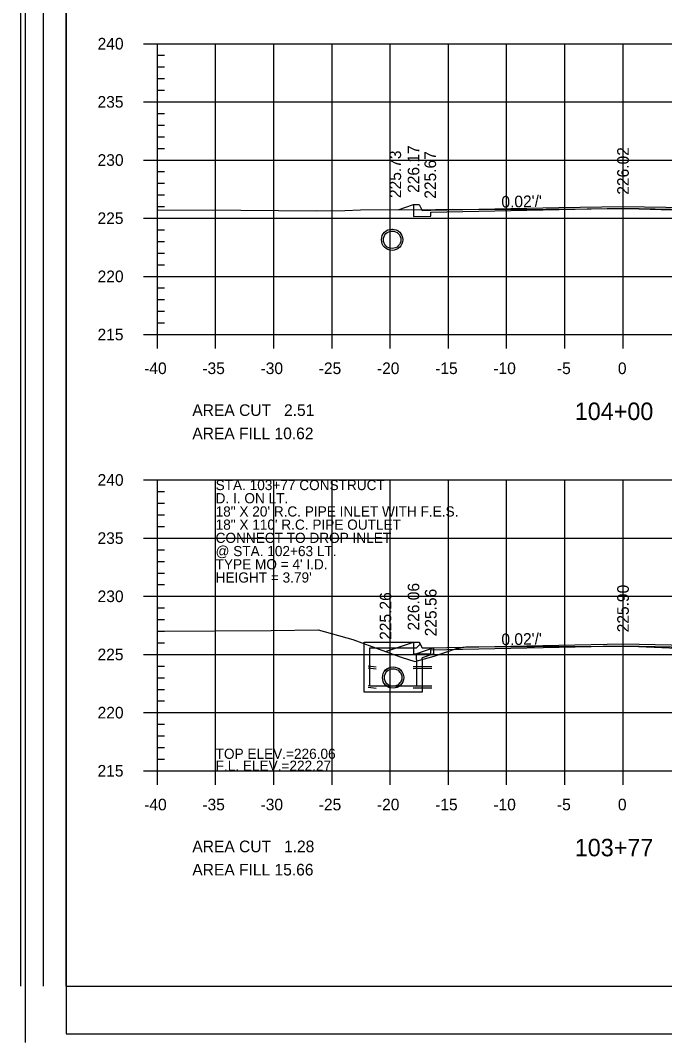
# Model space of a CAD drawing. Extents: x 1367903 to 1373764, y 376865 to 382130.
# Drawn here: x 1370689.3 to 1370800, y 377279.1 to 377454.8 of the extents above; entities that cross this region are included whole.
import ezdxf

# ---------------------------------------------------------------- set-up
doc = ezdxf.new("R2010")
doc.units = 0
for name, color, linetype in [('R_Axis', 7, 'Continuous'), ('R_Axis Annot', 7, 'Continuous'), ('R_Border', 7, 'Continuous'), ('R_Border PE', 7, 'Continuous'), ('R_Draft', 7, 'Continuous'), ('R_Exist Surface', 7, 'Continuous'), ('R_Fin Surface', 7, 'Continuous'), ('R_Fin Surface Annot', 7, 'Continuous'), ('R_Grid', 7, 'Continuous'), ('R_Water', 7, 'Continuous'), ('R_Water Annot', 7, 'Continuous')]:
    doc.layers.add(name, color=color, linetype=linetype)

msp = doc.modelspace()

# ---------------------------------------------------------------- linework, layer by layer
for p, q in [((1370748.37, 377347.95), (1370757.87, 377347.95)), ((1370748.37, 377344.95), (1370748.37, 377347.95)), ((1370758.03, 377347.62), (1370757.37, 377346.95)), ((1370758.03, 377347.62), (1370757.87, 377347.95)), ((1370749.37, 377344.95), (1370749.37, 377346.95)), ((1370749.37, 377346.95), (1370757.37, 377346.95)), ((1370760.37, 377346.99), (1370757.37, 377345.95)), ((1370757.37, 377344.95), (1370757.37, 377345.95)), ((1370760.37, 377345.93), (1370758.37, 377345.24)), ((1370758.37, 377344.95), (1370758.37, 377345.24))]:
    msp.add_line(p, q)
for points in [[(1370756.87, 377423.18), (1370756.87, 377422.52), (1370756.87, 377422.52), (1370756.87, 377421.15), (1370759.87, 377421.21), (1370759.87, 377421.88), (1370792.87, 377422.54), (1370825.87, 377421.88), (1370825.87, 377421.21), (1370828.87, 377421.15), (1370828.87, 377422.6), (1370842.87, 377422.88), (1370842.87, 377423.46)], [(1370756.87, 377347.95), (1370756.87, 377347.28), (1370756.87, 377347.28), (1370756.87, 377345.92), (1370759.87, 377345.98), (1370759.87, 377346.65), (1370792.87, 377347.31), (1370825.87, 377346.65), (1370825.87, 377345.98), (1370828.87, 377345.92), (1370828.87, 377347.36), (1370842.87, 377347.64), (1370842.87, 377348.23)], [(1370760.37, 377345.93), (1370760.37, 377346.99)]]:
    msp.add_lwpolyline(points)
at = {"layer": 'R_Axis'}
for p, q in [((1370710.47, 377450.84), (1370715.27, 377450.84)), ((1370712.87, 377400.84), (1370712.87, 377450.84)), ((1370712.87, 377448.84), (1370714.07, 377448.84)), ((1370712.87, 377446.84), (1370714.07, 377446.84)), ((1370712.87, 377444.84), (1370714.07, 377444.84)), ((1370712.87, 377442.84), (1370714.07, 377442.84)), ((1370710.47, 377440.84), (1370715.27, 377440.84)), ((1370712.87, 377438.84), (1370714.07, 377438.84)), ((1370712.87, 377436.84), (1370714.07, 377436.84)), ((1370712.87, 377434.84), (1370714.07, 377434.84)), ((1370712.87, 377432.84), (1370714.07, 377432.84)), ((1370710.47, 377430.84), (1370715.27, 377430.84)), ((1370712.87, 377428.84), (1370714.07, 377428.84)), ((1370712.87, 377426.84), (1370714.07, 377426.84)), ((1370712.87, 377424.84), (1370714.07, 377424.84)), ((1370712.87, 377422.84), (1370714.07, 377422.84)), ((1370710.47, 377420.84), (1370715.27, 377420.84)), ((1370712.87, 377418.84), (1370714.07, 377418.84)), ((1370712.87, 377416.84), (1370714.07, 377416.84)), ((1370712.87, 377414.84), (1370714.07, 377414.84)), ((1370712.87, 377412.84), (1370714.07, 377412.84)), ((1370710.47, 377410.84), (1370715.27, 377410.84)), ((1370712.87, 377408.84), (1370714.07, 377408.84)), ((1370712.87, 377406.84), (1370714.07, 377406.84)), ((1370712.87, 377404.84), (1370714.07, 377404.84)), ((1370712.87, 377398.44), (1370712.87, 377403.24)), ((1370712.87, 377402.84), (1370714.07, 377402.84)), ((1370722.87, 377398.44), (1370722.87, 377403.24)), ((1370732.87, 377398.44), (1370732.87, 377403.24)), ((1370742.87, 377398.44), (1370742.87, 377403.24)), ((1370752.87, 377398.44), (1370752.87, 377403.24)), ((1370762.87, 377398.44), (1370762.87, 377403.24)), ((1370772.87, 377398.44), (1370772.87, 377403.24)), ((1370782.87, 377398.44), (1370782.87, 377403.24)), ((1370792.87, 377398.44), (1370792.87, 377403.24)), ((1370710.47, 377400.84), (1370715.27, 377400.84)), ((1370712.87, 377400.84), (1370872.87, 377400.84)), ((1370710.47, 377375.84), (1370715.27, 377375.84)), ((1370712.87, 377325.84), (1370712.87, 377375.84)), ((1370712.87, 377373.84), (1370714.07, 377373.84)), ((1370712.87, 377371.84), (1370714.07, 377371.84)), ((1370712.87, 377369.84), (1370714.07, 377369.84)), ((1370712.87, 377367.84), (1370714.07, 377367.84)), ((1370710.47, 377365.84), (1370715.27, 377365.84)), ((1370712.87, 377363.84), (1370714.07, 377363.84)), ((1370712.87, 377361.84), (1370714.07, 377361.84)), ((1370712.87, 377359.84), (1370714.07, 377359.84)), ((1370712.87, 377357.84), (1370714.07, 377357.84)), ((1370710.47, 377355.84), (1370715.27, 377355.84)), ((1370712.87, 377353.84), (1370714.07, 377353.84)), ((1370712.87, 377351.84), (1370714.07, 377351.84)), ((1370712.87, 377349.84), (1370714.07, 377349.84)), ((1370712.87, 377347.84), (1370714.07, 377347.84)), ((1370710.47, 377345.84), (1370715.27, 377345.84)), ((1370712.87, 377343.84), (1370714.07, 377343.84)), ((1370712.87, 377341.84), (1370714.07, 377341.84)), ((1370712.87, 377339.84), (1370714.07, 377339.84)), ((1370712.87, 377337.84), (1370714.07, 377337.84)), ((1370710.47, 377335.84), (1370715.27, 377335.84)), ((1370712.87, 377333.84), (1370714.07, 377333.84)), ((1370712.87, 377331.84), (1370714.07, 377331.84)), ((1370712.87, 377329.84), (1370714.07, 377329.84)), ((1370712.87, 377323.44), (1370712.87, 377328.24)), ((1370712.87, 377327.84), (1370714.07, 377327.84)), ((1370722.87, 377323.44), (1370722.87, 377328.24)), ((1370732.87, 377323.44), (1370732.87, 377328.24)), ((1370742.87, 377323.44), (1370742.87, 377328.24)), ((1370752.87, 377323.44), (1370752.87, 377328.24)), ((1370762.87, 377323.44), (1370762.87, 377328.24)), ((1370772.87, 377323.44), (1370772.87, 377328.24)), ((1370782.87, 377323.44), (1370782.87, 377328.24)), ((1370792.87, 377323.44), (1370792.87, 377328.24)), ((1370710.47, 377325.84), (1370715.27, 377325.84)), ((1370712.87, 377325.84), (1370872.87, 377325.84))]:
    msp.add_line(p, q, dxfattribs=at)
at = {"layer": 'R_Border'}
for p, q in [((1370690.14, 377620.35), (1370690.14, 377279.12)), ((1370697.17, 377611.47), (1370697.17, 377280.59)), ((1370697.17, 377280.59), (1370901.49, 377280.59))]:
    msp.add_line(p, q, dxfattribs=at)
at = {"layer": 'R_Border PE'}
for p, q in [((1370689.33, 377610.76), (1370689.33, 377288.8)), ((1370693.25, 377610.76), (1370693.25, 377288.8)), ((1370697.17, 377288.8), (1370697.17, 377603.25)), ((1370697.17, 377288.8), (1370901.49, 377288.8))]:
    msp.add_line(p, q, dxfattribs=at)
at = {"layer": 'R_Exist Surface'}
for points in [[(1370712.87, 377422.27), (1370712.99, 377422.27), (1370727.18, 377422.21), (1370740.13, 377422.11), (1370745.07, 377422.14), (1370747.76, 377422.25), (1370760.67, 377422.34), (1370762.22, 377422.34), (1370762.23, 377422.34), (1370763.5, 377422.38), (1370772.68, 377422.35), (1370793.72, 377422.5), (1370801.33, 377422.29)], [(1370712.87, 377349.87), (1370732.39, 377349.96), (1370740.51, 377350.07), (1370746.45, 377348.41), (1370751.41, 377346.59), (1370754.74, 377345.36), (1370757.1, 377344.61), (1370760.4, 377345.52), (1370764.25, 377346.84), (1370764.41, 377346.88), (1370765.86, 377347.14), (1370789.45, 377347.26), (1370794.18, 377347.28), (1370799.52, 377347.03), (1370824.15, 377345.97), (1370826.34, 377345.73), (1370839.08, 377345.71), (1370843.6, 377345.67), (1370845.88, 377345.51), (1370849.36, 377345.47), (1370861.41, 377344.89), (1370867.07, 377344.65), (1370871.28, 377344.49), (1370872.87, 377344.43)]]:
    msp.add_lwpolyline(points, dxfattribs=at)
at = {"layer": 'R_Fin Surface'}
for points in [[(1370754.21, 377422.3), (1370756.87, 377423.18), (1370757.87, 377423.18), (1370758.37, 377422.18), (1370759.87, 377422.21), (1370781.87, 377422.65), (1370792.87, 377422.87), (1370803.87, 377422.65), (1370825.87, 377422.21), (1370827.37, 377422.18), (1370827.87, 377423.18), (1370828.87, 377423.18), (1370832.87, 377423.26), (1370842.87, 377423.46), (1370850.83, 377420.81)], [(1370752.06, 377346.35), (1370756.87, 377347.95), (1370757.87, 377347.95), (1370758.37, 377346.95), (1370759.87, 377346.98), (1370781.87, 377347.42), (1370792.87, 377347.64), (1370803.87, 377347.42), (1370825.87, 377346.98), (1370827.37, 377346.95), (1370827.87, 377347.95), (1370828.87, 377347.95), (1370832.87, 377348.03), (1370842.87, 377348.23), (1370851.44, 377345.37)]]:
    msp.add_lwpolyline(points, dxfattribs=at)
at = {"layer": 'R_Grid'}
for p, q in [((1370712.87, 377450.84), (1370872.87, 377450.84)), ((1370712.87, 377400.84), (1370712.87, 377450.84)), ((1370722.87, 377400.84), (1370722.87, 377450.84)), ((1370732.87, 377400.84), (1370732.87, 377450.84)), ((1370742.87, 377400.84), (1370742.87, 377450.84)), ((1370752.87, 377400.84), (1370752.87, 377450.84)), ((1370762.87, 377400.84), (1370762.87, 377450.84)), ((1370772.87, 377400.84), (1370772.87, 377450.84)), ((1370782.87, 377400.84), (1370782.87, 377450.84)), ((1370792.87, 377400.84), (1370792.87, 377450.84)), ((1370712.87, 377440.84), (1370872.87, 377440.84)), ((1370712.87, 377430.84), (1370872.87, 377430.84)), ((1370712.87, 377420.84), (1370872.87, 377420.84)), ((1370712.87, 377410.84), (1370872.87, 377410.84)), ((1370712.87, 377400.84), (1370872.87, 377400.84)), ((1370712.87, 377375.84), (1370872.87, 377375.84)), ((1370712.87, 377325.84), (1370712.87, 377375.84)), ((1370722.87, 377325.84), (1370722.87, 377375.84)), ((1370732.87, 377325.84), (1370732.87, 377375.84)), ((1370742.87, 377325.84), (1370742.87, 377375.84)), ((1370752.87, 377325.84), (1370752.87, 377375.84)), ((1370762.87, 377325.84), (1370762.87, 377375.84)), ((1370772.87, 377325.84), (1370772.87, 377375.84)), ((1370782.87, 377325.84), (1370782.87, 377375.84)), ((1370792.87, 377325.84), (1370792.87, 377375.84)), ((1370712.87, 377365.84), (1370872.87, 377365.84)), ((1370712.87, 377355.84), (1370872.87, 377355.84)), ((1370712.87, 377345.84), (1370872.87, 377345.84)), ((1370712.87, 377335.84), (1370872.87, 377335.84)), ((1370712.87, 377325.84), (1370872.87, 377325.84))]:
    msp.add_line(p, q, dxfattribs=at)
at = {"layer": 'R_Water'}
for p, q in [((1370753.2, 377418.99), (1370753.21, 377418.94)), ((1370753.2, 377418.66), (1370753.21, 377418.61)), ((1370753.2, 377415.66), (1370753.21, 377415.61)), ((1370753.2, 377415.32), (1370753.21, 377415.27)), ((1370749.07, 377343.87), (1370750.43, 377343.71)), ((1370760.04, 377343.73), (1370756.8, 377343.71)), ((1370749.07, 377343.53), (1370750.43, 377343.38)), ((1370760.04, 377343.4), (1370756.8, 377343.38)), ((1370749.07, 377340.53), (1370750.43, 377340.38)), ((1370749.07, 377340.2), (1370750.43, 377340.04)), ((1370760.04, 377340.4), (1370756.8, 377340.38)), ((1370760.04, 377340.06), (1370756.8, 377340.04))]:
    msp.add_line(p, q, dxfattribs=at)
for points in [[(1370758.37, 377344.95), (1370758.37, 377339.37), (1370753.37, 377339.37), (1370748.37, 377339.37), (1370748.37, 377344.95)], [(1370757.37, 377344.95), (1370757.37, 377340.37), (1370753.37, 377340.37), (1370749.37, 377340.37), (1370749.37, 377344.95)]]:
    msp.add_lwpolyline(points, dxfattribs=at)
for centre, radius in [((1370753.2, 377417.13), 1.83), ((1370753.2, 377417.13), 1.5), ((1370753.37, 377341.88), 1.83), ((1370753.37, 377341.87), 1.83), ((1370753.37, 377341.88), 1.5), ((1370753.37, 377341.87), 1.5)]:
    msp.add_circle(centre, radius, dxfattribs=at)

# ---------------------------------------------------------------- texts
at = {"layer": 'R_Axis Annot'}
for s, height, p in [('240', 2, (1370702.59, 377449.84)), ('235', 2, (1370702.58, 377439.84)), ('230', 2, (1370702.59, 377429.84)), ('225', 2, (1370702.58, 377419.84)), ('220', 2, (1370702.59, 377409.84)), ('215', 2, (1370702.58, 377399.84)), ('-40', 2, (1370710.59, 377394.04)), ('-35', 2, (1370720.59, 377394.04)), ('-30', 2, (1370730.59, 377394.04)), ('-25', 2, (1370740.59, 377394.04)), ('-20', 2, (1370750.59, 377394.04)), ('-15', 2, (1370760.59, 377394.04)), ('-10', 2, (1370770.59, 377394.04)), ('-5', 2, (1370781.52, 377394.04)), ('0', 2, (1370791.99, 377394.04)), ('AREA CUT   2.51', 2, (1370718.87, 377386.84)), ('104+00', 3, (1370784.58, 377386.14)), ('AREA FILL 10.62', 2, (1370718.87, 377382.84)), ('240', 2, (1370702.59, 377374.84)), ('235', 2, (1370702.58, 377364.84)), ('230', 2, (1370702.59, 377354.84)), ('225', 2, (1370702.58, 377344.84)), ('220', 2, (1370702.59, 377334.84)), ('215', 2, (1370702.58, 377324.84)), ('-40', 2, (1370710.59, 377319.04)), ('-35', 2, (1370720.59, 377319.04)), ('-30', 2, (1370730.59, 377319.04)), ('-25', 2, (1370740.59, 377319.04)), ('-20', 2, (1370750.59, 377319.04)), ('-15', 2, (1370760.59, 377319.04)), ('-10', 2, (1370770.59, 377319.04)), ('-5', 2, (1370781.52, 377319.04)), ('0', 2, (1370791.99, 377319.04)), ('AREA CUT   1.28', 2, (1370718.87, 377311.84)), ('103+77', 3, (1370784.58, 377311.14)), ('AREA FILL 15.66', 2, (1370718.87, 377307.84))]:
    msp.add_text(s, height=height, dxfattribs=at).set_placement(p)
at = {"layer": 'R_Draft'}
for s, p in [('STA. 103+77 CONSTRUCT', (1370722.87, 377374.09)), ('D. I. ON LT.', (1370722.87, 377371.82)), ('18" X 20\' R.C. PIPE INLET WITH F.E.S.', (1370722.87, 377369.55)), ('18" X 110\' R.C. PIPE OUTLET', (1370722.87, 377367.28)), ('CONNECT TO DROP INLET', (1370722.87, 377365.01)), ('@ STA. 102+63 LT.', (1370722.87, 377362.74)), ("TYPE MO = 4' I.D.", (1370722.87, 377360.47)), ("HEIGHT = 3.79'", (1370722.87, 377358.2))]:
    msp.add_text(s, height=1.75, dxfattribs=at).set_placement(p)
at = {"layer": 'R_Fin Surface Annot'}
for s, rotation, p in [('226.17', 90, (1370757.87, 377425.18)), ('225.73', 90, (1370754.74, 377424.3)), ('225.67', 90, (1370760.75, 377424.18)), ('226.02', 90, (1370793.87, 377424.87)), ("0.02'/'", 1.1458, (1370771.99, 377422.65)), ('226.06', 90, (1370757.87, 377349.95)), ('225.90', 90, (1370793.87, 377349.64)), ('225.26', 90, (1370753.06, 377348.35)), ('225.56', 90, (1370760.83, 377348.95)), ("0.02'/'", 1.1456, (1370771.99, 377347.42))]:
    msp.add_text(s, height=2, rotation=rotation, dxfattribs=at).set_placement(p)
at = {"layer": 'R_Water Annot'}
for s, p in [('TOP ELEV.=226.06', (1370722.87, 377327.89)), ('F.L. ELEV.=222.27', (1370722.87, 377325.84))]:
    msp.add_text(s, height=1.75, dxfattribs=at).set_placement(p)

doc.saveas('drawing.dxf')
